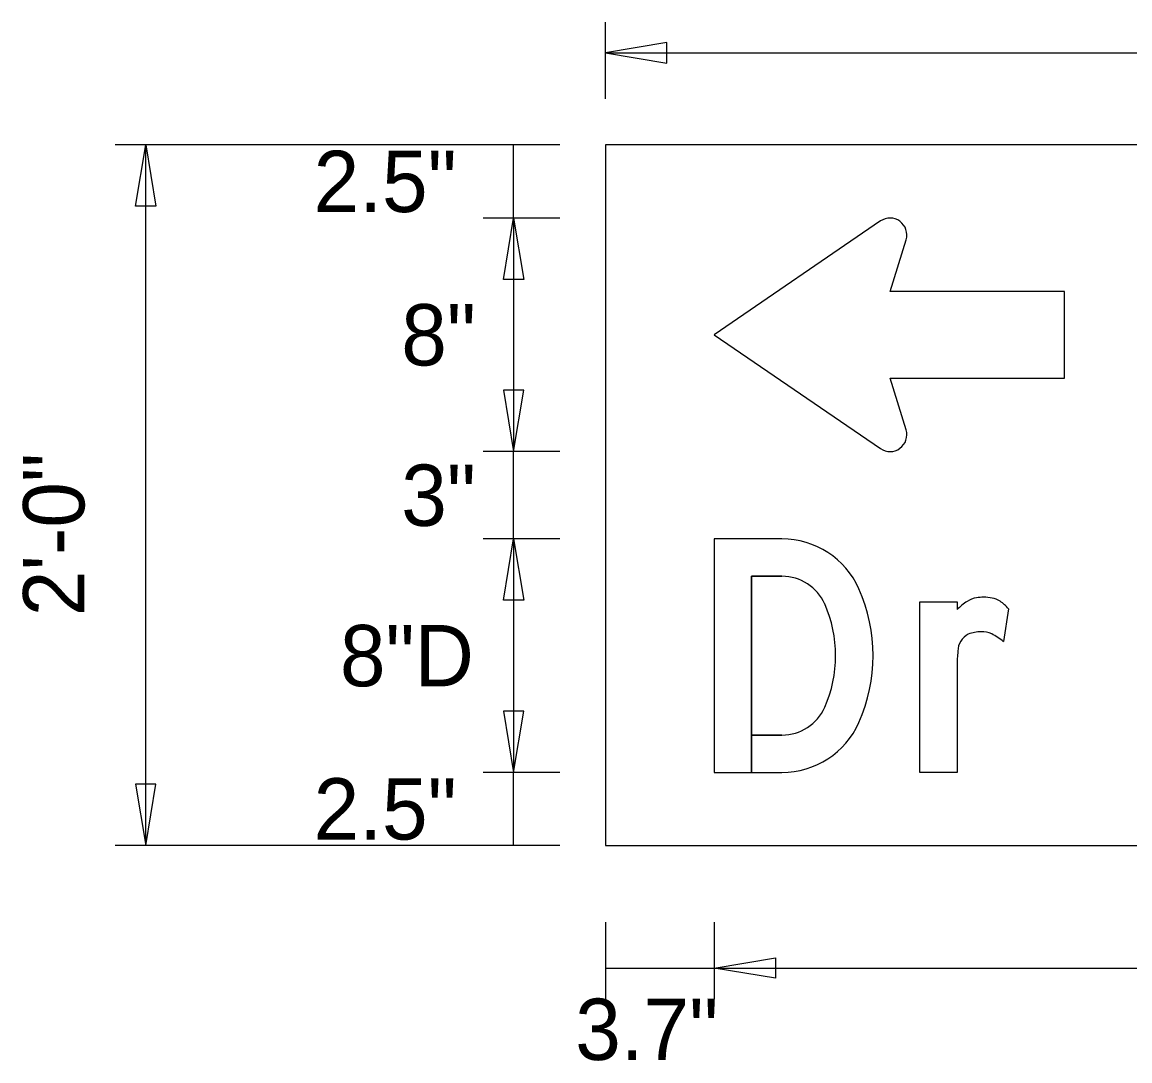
# Model space of a CAD drawing. Extents: x 1374 to 1480, y 568 to 638.
# Drawn here: x 1413.193 to 1416.354, y 624.529 to 627.494 of the extents above; entities that cross this region are included whole.
import ezdxf

# ---------------------------------------------------------------- set-up
doc = ezdxf.new("R2010")
doc.units = 0
for name, color, linetype in [('GSBWFill', 7, 'Continuous'), ('GSColorFill', 7, 'Continuous'), ('GSDims', 7, 'Continuous'), ('GSOutline', 7, 'Continuous')]:
    doc.layers.add(name, color=color, linetype=linetype)

msp = doc.modelspace()

# ---------------------------------------------------------------- linework, layer by layer
at = {"layer": 'GSBWFill'}
for p, q in [((1423.8581, 627.1437), (1414.8581, 627.1437)), ((1414.8581, 627.1437), (1414.8581, 625.1437)), ((1416.0078, 625.8192), (1415.9936, 625.7253)), ((1416.0078, 625.8192), (1416.0078, 625.8192)), ((1415.3613, 625.4587), (1415.2745, 625.4587)), ((1414.8581, 625.1437), (1423.8581, 625.1437))]:
    msp.add_line(p, q, dxfattribs=at)
for points in [[(1415.6423, 626.9261), (1415.1678, 626.6012), (1415.6423, 626.2763)], [(1416.1678, 626.4775), (1416.1678, 626.7249), (1415.6702, 626.7249), (1415.7155, 626.8723)], [(1415.7155, 626.3301), (1415.6702, 626.4775), (1416.1678, 626.4775)], [(1415.3613, 626.0187), (1415.1678, 626.0187), (1415.1678, 625.352), (1415.2744, 625.352), (1415.2744, 625.912), (1415.3613, 625.912)], [(1415.8611, 625.6572), (1415.8611, 625.352), (1415.7544, 625.352), (1415.7544, 625.8387), (1415.8611, 625.8387), (1415.8611, 625.8168)], [(1415.2745, 625.4587), (1415.2745, 625.352), (1415.3613, 625.352)]]:
    msp.add_lwpolyline(points, dxfattribs=at)
for centre, start, end in [((1415.6695, 626.8864), 342.9427, 124.3997), ((1415.6695, 626.316), 235.6003, 17.0573)]:
    msp.add_arc(centre, 0.0481, start, end, dxfattribs=at)
for centre, major_axis, ratio, start_param, end_param in [((1415.3613, 625.7787), (0, 0.24), 0.999999, 5.13024, 6.283185), ((1415.3613, 625.7787), (0, 0.1333), 0.999999, 5.13024, 6.283185), ((1415.1511, 625.6854), (0, 0.47), 0.999999, 4.294538, 5.13024), ((1415.9893, 625.689), (0, 0.181), 0.999998, 0.581368, 0.786698), ((1415.9265, 625.7846), (0, 0.0667), 0.999998, 0.152837, 0.581368), ((1415.9368, 625.7175), (0, 0.1345), 0.999998, 0, 0.152837), ((1415.9368, 625.7272), (0, 0.1248), 0.999998, 6.089185, 6.283185), ((1415.948, 625.7843), (0, 0.0667), 0.999998, 5.719052, 6.089185), ((1415.9303, 625.7563), (0, 0.0997), 0.999998, 5.39423, 5.719052), ((1415.1511, 625.6854), (0, 0.3633), 0.999999, 4.294538, 5.13024), ((1415.919, 625.6976), (0, 0.0558), 0.999998, 0.483758, 1.563151), ((1415.9297, 625.6461), (0, 0.1073), 0.999998, 0, 0.348596), ((1415.9297, 625.6752), (0, 0.0783), 0.999998, 5.88958, 6.283185), ((1415.8745, 625.5806), (0, 0.1873), 0.999998, 5.594805, 5.811282), ((1416.2637, 625.6572), (0, 0.4026), 0.999998, 1.469323, 1.570796), ((1415.3613, 625.592), (0, 0.1333), 0.999999, 3.141593, 4.294538), ((1415.3613, 625.592), (0, 0.24), 0.999999, 3.141593, 4.294538)]:
    msp.add_ellipse(centre, major_axis=major_axis, ratio=ratio, start_param=start_param, end_param=end_param, dxfattribs=at)
at = {"layer": 'GSColorFill'}
for p, q in [((1423.8581, 627.1437), (1414.8581, 627.1437)), ((1414.8581, 627.1437), (1414.8581, 625.1437)), ((1423.8581, 627.1437), (1414.8581, 627.1437)), ((1414.8581, 627.1437), (1414.8581, 625.1437)), ((1416.0078, 625.8192), (1415.9936, 625.7253)), ((1416.0078, 625.8192), (1416.0078, 625.8192)), ((1415.3613, 625.4587), (1415.2745, 625.4587)), ((1414.8581, 625.1437), (1423.8581, 625.1437)), ((1414.8581, 625.1437), (1423.8581, 625.1437))]:
    msp.add_line(p, q, dxfattribs=at)
for points in [[(1415.6423, 626.9261), (1415.1678, 626.6012), (1415.6423, 626.2763)], [(1416.1678, 626.4775), (1416.1678, 626.7249), (1415.6702, 626.7249), (1415.7155, 626.8723)], [(1415.7155, 626.3301), (1415.6702, 626.4775), (1416.1678, 626.4775)], [(1415.3613, 626.0187), (1415.1678, 626.0187), (1415.1678, 625.352), (1415.2744, 625.352), (1415.2744, 625.912), (1415.3613, 625.912)], [(1415.8611, 625.6572), (1415.8611, 625.352), (1415.7544, 625.352), (1415.7544, 625.8387), (1415.8611, 625.8387), (1415.8611, 625.8168)], [(1415.2745, 625.4587), (1415.2745, 625.352), (1415.3613, 625.352)]]:
    msp.add_lwpolyline(points, dxfattribs=at)
for centre, start, end in [((1415.6695, 626.8864), 342.9427, 124.3997), ((1415.6695, 626.316), 235.6003, 17.0573)]:
    msp.add_arc(centre, 0.0481, start, end, dxfattribs=at)
for centre, major_axis, ratio, start_param, end_param in [((1415.3613, 625.7787), (0, 0.24), 0.999999, 5.13024, 6.283185), ((1415.3613, 625.7787), (0, 0.1333), 0.999999, 5.13024, 6.283185), ((1415.1511, 625.6854), (0, 0.47), 0.999999, 4.294538, 5.13024), ((1415.9893, 625.689), (0, 0.181), 0.999998, 0.581368, 0.786698), ((1415.9265, 625.7846), (0, 0.0667), 0.999998, 0.152837, 0.581368), ((1415.9368, 625.7175), (0, 0.1345), 0.999998, 0, 0.152837), ((1415.9368, 625.7272), (0, 0.1248), 0.999998, 6.089185, 6.283185), ((1415.948, 625.7843), (0, 0.0667), 0.999998, 5.719052, 6.089185), ((1415.9303, 625.7563), (0, 0.0997), 0.999998, 5.39423, 5.719052), ((1415.1511, 625.6854), (0, 0.3633), 0.999999, 4.294538, 5.13024), ((1415.919, 625.6976), (0, 0.0558), 0.999998, 0.483758, 1.563151), ((1415.9297, 625.6461), (0, 0.1073), 0.999998, 0, 0.348596), ((1415.9297, 625.6752), (0, 0.0783), 0.999998, 5.88958, 6.283185), ((1415.8745, 625.5806), (0, 0.1873), 0.999998, 5.594805, 5.811282), ((1416.2637, 625.6572), (0, 0.4026), 0.999998, 1.469323, 1.570796), ((1415.3613, 625.592), (0, 0.1333), 0.999999, 3.141593, 4.294538), ((1415.3613, 625.592), (0, 0.24), 0.999999, 3.141593, 4.294538)]:
    msp.add_ellipse(centre, major_axis=major_axis, ratio=ratio, start_param=start_param, end_param=end_param, dxfattribs=at)
at = {"layer": 'GSDims'}
for p, q in [((1414.8581, 627.275), (1414.8581, 627.4937)), ((1414.8581, 627.4062), (1423.8581, 627.4062)), ((1414.8581, 627.275), (1414.8581, 627.275)), ((1413.6769, 627.1437), (1413.4581, 627.1437)), ((1413.5456, 625.1437), (1413.5456, 627.1437)), ((1414.7269, 627.1437), (1413.6769, 627.1437)), ((1414.7269, 627.1437), (1414.5081, 627.1437)), ((1414.5956, 626.9345), (1414.5956, 627.1437)), ((1414.7269, 626.9345), (1414.5081, 626.9345)), ((1414.7269, 626.9345), (1414.5081, 626.9345)), ((1414.5956, 626.9345), (1414.5956, 626.2679)), ((1414.7269, 626.2679), (1414.5081, 626.2679)), ((1414.7269, 626.2679), (1414.5081, 626.2679)), ((1414.5956, 626.0187), (1414.5956, 626.2679)), ((1414.7269, 626.0187), (1414.5081, 626.0187)), ((1414.7269, 626.0187), (1414.5081, 626.0187)), ((1414.5956, 626.0187), (1414.5956, 625.352)), ((1414.7269, 625.352), (1414.5081, 625.352)), ((1414.7269, 625.352), (1414.5081, 625.352)), ((1414.5956, 625.1437), (1414.5956, 625.352)), ((1413.6769, 625.1437), (1413.4581, 625.1437)), ((1414.7269, 625.1437), (1413.6769, 625.1437)), ((1414.7269, 625.1437), (1414.5081, 625.1437)), ((1414.8581, 624.9249), (1414.8581, 624.7062)), ((1414.8581, 624.9249), (1414.8581, 624.7062)), ((1415.1678, 624.9249), (1415.1678, 624.7062)), ((1415.1678, 624.9249), (1415.1678, 624.7062)), ((1414.8581, 624.7937), (1415.1678, 624.7937)), ((1415.1678, 624.7937), (1423.5478, 624.7937))]:
    msp.add_line(p, q, dxfattribs=at)
for points in [[(1414.8581, 627.4062), (1415.0331, 627.377), (1415.0331, 627.4354)], [(1413.5456, 627.1437), (1413.5748, 626.9687), (1413.5165, 626.9687)], [(1414.5956, 626.9345), (1414.6248, 626.7595), (1414.5665, 626.7595)], [(1414.5956, 626.2679), (1414.6248, 626.4429), (1414.5665, 626.4429)], [(1414.5956, 626.0187), (1414.6248, 625.8437), (1414.5665, 625.8437)], [(1414.5956, 625.352), (1414.6248, 625.527), (1414.5665, 625.527)], [(1413.5456, 625.1437), (1413.5748, 625.3187), (1413.5165, 625.3187)], [(1415.1678, 624.7937), (1415.3428, 624.8229), (1415.3428, 624.7645)]]:
    msp.add_lwpolyline(points, close=True, dxfattribs=at)
at = {"layer": 'GSOutline'}
for p, q in [((1423.8581, 627.1437), (1414.8581, 627.1437)), ((1414.8581, 627.1437), (1414.8581, 625.1437)), ((1415.3613, 626.0187), (1415.1678, 626.0187)), ((1415.3613, 625.912), (1415.2744, 625.912)), ((1416.0078, 625.8192), (1415.9936, 625.7253)), ((1416.0078, 625.8192), (1416.0078, 625.8192)), ((1414.8581, 625.1437), (1423.8581, 625.1437))]:
    msp.add_line(p, q, dxfattribs=at)
for points in [[(1415.6423, 626.9261), (1415.1678, 626.6012), (1415.6423, 626.2763)], [(1416.1678, 626.4775), (1416.1678, 626.7249), (1415.6702, 626.7249), (1415.7155, 626.8723)], [(1415.7155, 626.3301), (1415.6702, 626.4775), (1416.1678, 626.4775)], [(1415.1678, 626.0187), (1415.1678, 625.352), (1415.3613, 625.352)], [(1415.2744, 625.912), (1415.2744, 625.4587), (1415.3613, 625.4587)], [(1415.8611, 625.6572), (1415.8611, 625.352), (1415.7544, 625.352), (1415.7544, 625.8387), (1415.8611, 625.8387), (1415.8611, 625.8168)]]:
    msp.add_lwpolyline(points, dxfattribs=at)
for centre, start, end in [((1415.6695, 626.8864), 342.9427, 124.3997), ((1415.6695, 626.316), 235.6003, 17.0573)]:
    msp.add_arc(centre, 0.0481, start, end, dxfattribs=at)
for centre, major_axis, ratio, start_param, end_param in [((1415.3613, 625.7787), (0, 0.24), 0.999999, 5.13024, 6.283185), ((1415.3613, 625.7787), (0, 0.1333), 0.999999, 5.13024, 6.283185), ((1415.1511, 625.6854), (0, 0.47), 0.999999, 4.294538, 5.13024), ((1415.9893, 625.689), (0, 0.181), 0.999998, 0.581368, 0.786698), ((1415.9265, 625.7846), (0, 0.0667), 0.999998, 0.152837, 0.581368), ((1415.9368, 625.7175), (0, 0.1345), 0.999998, 0, 0.152837), ((1415.9368, 625.7272), (0, 0.1248), 0.999998, 6.089185, 6.283185), ((1415.948, 625.7843), (0, 0.0667), 0.999998, 5.719052, 6.089185), ((1415.9303, 625.7563), (0, 0.0997), 0.999998, 5.39423, 5.719052), ((1415.1511, 625.6854), (0, 0.3633), 0.999999, 4.294538, 5.13024), ((1415.919, 625.6976), (0, 0.0558), 0.999998, 0.483758, 1.563151), ((1415.9297, 625.6461), (0, 0.1073), 0.999998, 0, 0.348596), ((1415.9297, 625.6752), (0, 0.0783), 0.999998, 5.88958, 6.283185), ((1415.8745, 625.5806), (0, 0.1873), 0.999998, 5.594805, 5.811282), ((1416.2637, 625.6572), (0, 0.4026), 0.999998, 1.469323, 1.570796), ((1415.3613, 625.592), (0, 0.1333), 0.999999, 3.141593, 4.294538), ((1415.3613, 625.592), (0, 0.24), 0.999999, 3.141593, 4.294538)]:
    msp.add_ellipse(centre, major_axis=major_axis, ratio=ratio, start_param=start_param, end_param=end_param, dxfattribs=at)

# ---------------------------------------------------------------- texts
at = {"layer": 'GSDims'}
for s, p in [('2.5"', (1414.0248, 626.9516)), ('8"', (1414.2748, 626.5137)), ('3"', (1414.2748, 626.0558)), ('8"D', (1414.0998, 625.5979)), ('2.5"', (1414.0248, 625.1604)), ('3.7"', (1414.7713, 624.5312))]:
    msp.add_text(s, height=0.175, dxfattribs=at).set_placement(p)
msp.add_text('2\'-0"', height=0.175, rotation=90, dxfattribs=at).set_placement((1413.3706, 625.7979))

doc.saveas('drawing.dxf')
